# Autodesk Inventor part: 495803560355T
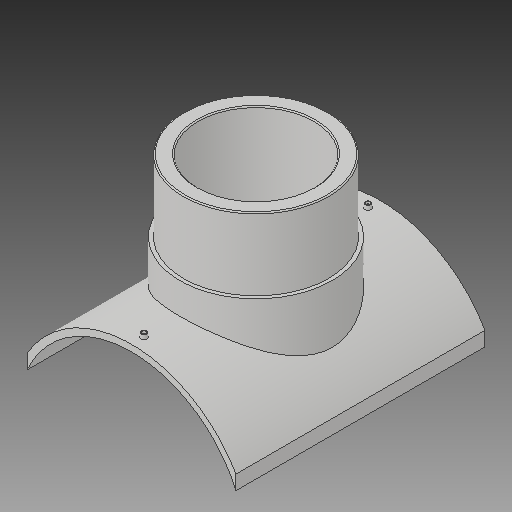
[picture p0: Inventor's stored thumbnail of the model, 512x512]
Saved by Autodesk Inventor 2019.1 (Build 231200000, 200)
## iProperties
Created: 2017-10
Part Number: 495803560355T
Material: Generic
Description: PLASSON BRANCH SADDLE  560x355
Document SubType Name: Modeling
Designer: KIM
Mass: 2754.05 g
Surface Area: 3037.44 cm^2
Volume: 2754.05 cm^3
Density: 1 g/cm^3
Appearance: Default
Author: KIM
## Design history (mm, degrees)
derived "495803.ipt"
feature "Solid1::495803.ipt"
tag "TaggingFeature1"
body "Solid1"
other parameters: "d1" = 16, "d2" = 512, "d4" = 0, "d12" = 305.6, "d13" = 14, "d14" = 274.5, "d16" = 5 deg, "d18" = 4, "d19" = 14, "d20" = 0, "d21" = 3, "d22" = 0, "d23" = 548, "d24" = 372.75, "d25" = 16, "d26" = 284, "d28" = 0, "d29" = 9.6, "d31" = 0, "d32" = 126, "d33" = 0, "d34" = 5.6, "d36" = 355, "d37" = 176.4, "d38" = 0, "d39" = 2.8, "d_1" = 355, "B_" = 512, "H_" = 252, "x_" = 16, "D_" = 16
